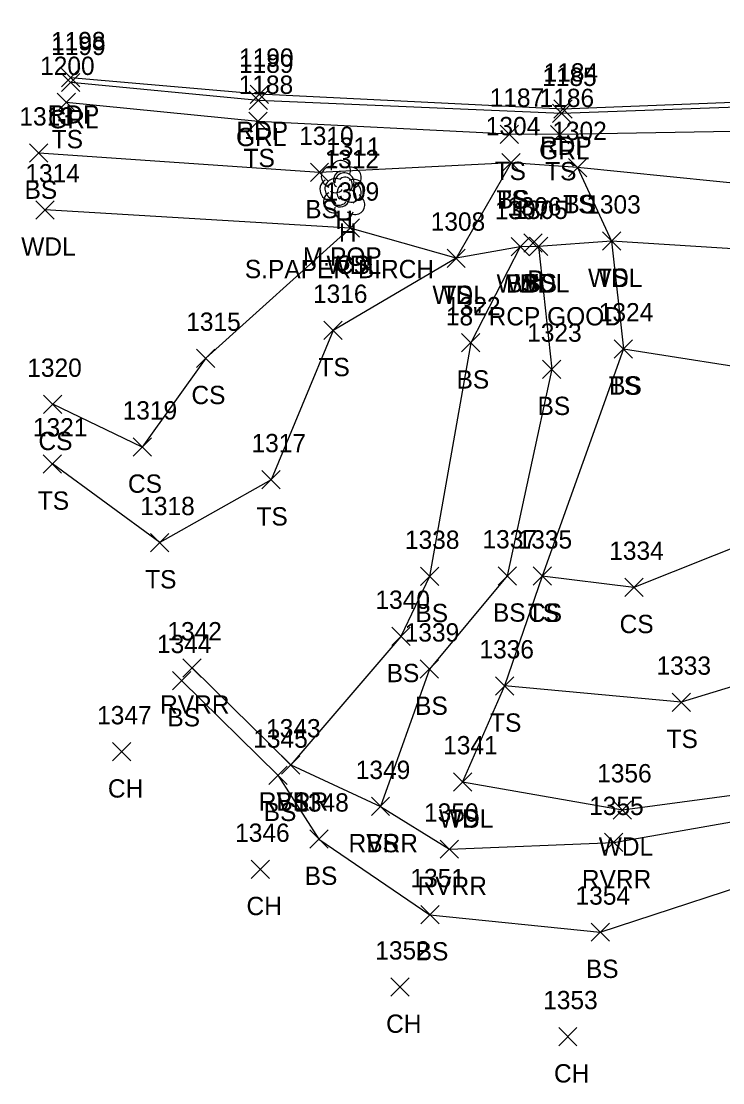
# Model space of a CAD drawing. Extents: x 1502119 to 1504100, y 606168 to 606406.
# Drawn here: x 1503596.2 to 1503672.8, y 606167.8 to 606283.7 of the extents above; entities that cross this region are included whole.
import ezdxf

# ---------------------------------------------------------------- set-up
doc = ezdxf.new("R2010")
doc.units = 0
for name, color, linetype in [('D_A', 7, 'Continuous'), ('D_C', 7, 'Continuous'), ('D_I', 7, 'Continuous'), ('D_TIC', 7, 'Continuous'), ('L_A', 7, 'Continuous'), ('L_C', 7, 'Continuous'), ('L_I', 7, 'Continuous'), ('L_TIC', 7, 'Continuous'), ('LAWA', 7, 'Continuous'), ('LAWE', 7, 'Continuous'), ('LELB', 7, 'Continuous'), ('LTD', 7, 'Continuous'), ('P_A', 7, 'Continuous'), ('P_I', 7, 'Continuous'), ('P_TIC', 7, 'Continuous'), ('PET', 7, 'Continuous'), ('R_A', 7, 'Continuous'), ('R_I', 7, 'Continuous'), ('R_TIC', 7, 'Continuous'), ('RGR', 7, 'Continuous')]:
    doc.layers.add(name, color=color, linetype=linetype)

msp = doc.modelspace()

# ---------------------------------------------------------------- linework, layer by layer
at = {"layer": 'D_TIC'}
for points in [[(1503651.06, 606258.48), (1503653.06, 606260.48)], [(1503653.06, 606258.48), (1503651.06, 606260.48)]]:
    msp.add_lwpolyline(points, dxfattribs=at)
at = {"layer": 'L_TIC'}
for points in [[(1503600.12, 606273.82), (1503602.12, 606275.82)], [(1503602.12, 606273.82), (1503600.12, 606275.82)], [(1503621.06, 606271.76), (1503623.06, 606273.76)], [(1503623.06, 606271.76), (1503621.06, 606273.76)], [(1503648.47, 606270.35), (1503650.47, 606272.35)], [(1503650.47, 606270.35), (1503648.47, 606272.35)], [(1503653.98, 606270.32), (1503655.98, 606272.32)], [(1503655.98, 606270.32), (1503653.98, 606272.32)], [(1503597.12, 606268.3), (1503599.12, 606270.3)], [(1503599.12, 606268.3), (1503597.12, 606270.3)], [(1503648.68, 606267.24), (1503650.68, 606269.24)], [(1503650.68, 606267.24), (1503648.68, 606269.24)], [(1503648.68, 606267.24), (1503650.68, 606269.24)], [(1503650.68, 606267.24), (1503648.68, 606269.24)], [(1503648.68, 606267.24), (1503650.68, 606269.24)], [(1503650.68, 606267.24), (1503648.68, 606269.24)], [(1503627.76, 606266.18), (1503629.76, 606268.18)], [(1503629.76, 606266.18), (1503627.76, 606268.18)], [(1503655.94, 606266.72), (1503657.94, 606268.72)], [(1503657.94, 606266.72), (1503655.94, 606268.72)], [(1503655.94, 606266.72), (1503657.94, 606268.72)], [(1503657.94, 606266.72), (1503655.94, 606268.72)], [(1503597.78, 606262.09), (1503599.78, 606264.09)], [(1503599.78, 606262.09), (1503597.78, 606264.09)], [(1503631.11, 606260.1), (1503633.11, 606262.1)], [(1503633.11, 606260.1), (1503631.11, 606262.1)], [(1503631.11, 606260.1), (1503633.11, 606262.1)], [(1503633.11, 606260.1), (1503631.11, 606262.1)], [(1503649.68, 606258.07), (1503651.68, 606260.07)], [(1503651.68, 606258.07), (1503649.68, 606260.07)], [(1503649.68, 606258.07), (1503651.68, 606260.07)], [(1503651.68, 606258.07), (1503649.68, 606260.07)], [(1503651.68, 606258.1), (1503653.68, 606260.1)], [(1503653.68, 606258.1), (1503651.68, 606260.1)], [(1503651.68, 606258.1), (1503653.68, 606260.1)], [(1503653.68, 606258.1), (1503651.68, 606260.1)], [(1503659.65, 606258.69), (1503661.65, 606260.69)], [(1503661.65, 606258.69), (1503659.65, 606260.69)], [(1503659.65, 606258.69), (1503661.65, 606260.69)], [(1503661.65, 606258.69), (1503659.65, 606260.69)], [(1503642.68, 606256.82), (1503644.68, 606258.82)], [(1503644.68, 606256.82), (1503642.68, 606258.82)], [(1503642.68, 606256.82), (1503644.68, 606258.82)], [(1503644.68, 606256.82), (1503642.68, 606258.82)], [(1503629.24, 606248.94), (1503631.24, 606250.94)], [(1503631.24, 606248.94), (1503629.24, 606250.94)], [(1503644.27, 606247.59), (1503646.27, 606249.59)], [(1503646.27, 606247.59), (1503644.27, 606249.59)], [(1503660.94, 606246.92), (1503662.94, 606248.92)], [(1503662.94, 606246.92), (1503660.94, 606248.92)], [(1503660.94, 606246.92), (1503662.94, 606248.92)], [(1503662.94, 606246.92), (1503660.94, 606248.92)], [(1503615.34, 606245.89), (1503617.34, 606247.89)], [(1503617.34, 606245.89), (1503615.34, 606247.89)], [(1503653.12, 606244.7), (1503655.12, 606246.7)], [(1503655.12, 606244.7), (1503653.12, 606246.7)], [(1503598.64, 606240.87), (1503600.64, 606242.87)], [(1503600.64, 606240.87), (1503598.64, 606242.87)], [(1503608.41, 606236.21), (1503610.41, 606238.21)], [(1503610.41, 606236.21), (1503608.41, 606238.21)], [(1503598.6, 606234.36), (1503600.6, 606236.36)], [(1503600.6, 606234.36), (1503598.6, 606236.36)], [(1503622.47, 606232.64), (1503624.47, 606234.64)], [(1503624.47, 606232.64), (1503622.47, 606234.64)], [(1503610.32, 606225.77), (1503612.32, 606227.77)], [(1503612.32, 606225.77), (1503610.32, 606227.77)], [(1503639.78, 606222.09), (1503641.78, 606224.09)], [(1503641.78, 606222.09), (1503639.78, 606224.09)], [(1503648.25, 606222.14), (1503650.25, 606224.14)], [(1503650.25, 606222.14), (1503648.25, 606224.14)], [(1503652.08, 606222.12), (1503654.08, 606224.12)], [(1503654.08, 606222.12), (1503652.08, 606224.12)], [(1503652.08, 606222.12), (1503654.08, 606224.12)], [(1503654.08, 606222.12), (1503652.08, 606224.12)], [(1503662.08, 606220.89), (1503664.08, 606222.89)], [(1503664.08, 606220.89), (1503662.08, 606222.89)], [(1503636.65, 606215.54), (1503638.65, 606217.54)], [(1503638.65, 606215.54), (1503636.65, 606217.54)], [(1503613.85, 606212.1), (1503615.85, 606214.1)], [(1503615.85, 606212.1), (1503613.85, 606214.1)], [(1503639.76, 606211.97), (1503641.76, 606213.97)], [(1503641.76, 606211.97), (1503639.76, 606213.97)], [(1503612.71, 606210.71), (1503614.71, 606212.71)], [(1503614.71, 606210.71), (1503612.71, 606212.71)], [(1503647.97, 606210.13), (1503649.97, 606212.13)], [(1503649.97, 606210.13), (1503647.97, 606212.13)], [(1503647.97, 606210.13), (1503649.97, 606212.13)], [(1503649.97, 606210.13), (1503647.97, 606212.13)], [(1503667.25, 606208.35), (1503669.25, 606210.35)], [(1503669.25, 606208.35), (1503667.25, 606210.35)], [(1503606.17, 606202.94), (1503608.17, 606204.94)], [(1503608.17, 606202.94), (1503606.17, 606204.94)], [(1503624.62, 606201.51), (1503626.62, 606203.51)], [(1503626.62, 606201.51), (1503624.62, 606203.51)], [(1503624.62, 606201.51), (1503626.62, 606203.51)], [(1503626.62, 606201.51), (1503624.62, 606203.51)], [(1503623.23, 606200.38), (1503625.23, 606202.38)], [(1503625.23, 606200.38), (1503623.23, 606202.38)], [(1503643.38, 606199.66), (1503645.38, 606201.66)], [(1503645.38, 606199.66), (1503643.38, 606201.66)], [(1503643.38, 606199.66), (1503645.38, 606201.66)], [(1503645.38, 606199.66), (1503643.38, 606201.66)], [(1503634.42, 606196.97), (1503636.42, 606198.97)], [(1503636.42, 606196.97), (1503634.42, 606198.97)], [(1503634.42, 606196.97), (1503636.42, 606198.97)], [(1503636.42, 606196.97), (1503634.42, 606198.97)], [(1503660.82, 606196.6), (1503662.82, 606198.6)], [(1503662.82, 606196.6), (1503660.82, 606198.6)], [(1503627.7, 606193.41), (1503629.7, 606195.41)], [(1503629.7, 606193.41), (1503627.7, 606195.41)], [(1503659.89, 606193.04), (1503661.89, 606195.04)], [(1503661.89, 606193.04), (1503659.89, 606195.04)], [(1503641.95, 606192.31), (1503643.95, 606194.31)], [(1503643.95, 606192.31), (1503641.95, 606194.31)], [(1503621.3, 606190.11), (1503623.3, 606192.11)], [(1503623.3, 606190.11), (1503621.3, 606192.11)], [(1503639.82, 606185.16), (1503641.82, 606187.16)], [(1503641.82, 606185.16), (1503639.82, 606187.16)], [(1503658.4, 606183.25), (1503660.4, 606185.25)], [(1503660.4, 606183.25), (1503658.4, 606185.25)], [(1503636.54, 606177.26), (1503638.54, 606179.26)], [(1503638.54, 606177.26), (1503636.54, 606179.26)], [(1503654.87, 606171.84), (1503656.87, 606173.84)], [(1503656.87, 606171.84), (1503654.87, 606173.84)]]:
    msp.add_lwpolyline(points, dxfattribs=at)
at = {"layer": 'LAWA'}
for points in [[(1503949.06, 606292.95), (1503922.72, 606291.41), (1503895.88, 606293.14), (1503871.23, 606284.55), (1503848.49, 606280.84), (1503822.63, 606273.75), (1503793.16, 606269.59), (1503770.58, 606267.1), (1503744.52, 606264.72), (1503721.39, 606263.89), (1503714.66, 606265.31), (1503698.22, 606260.24), (1503685.38, 606258.11), (1503660.65, 606259.69), (1503652.68, 606259.1), (1503650.68, 606259.07), (1503643.68, 606257.82), (1503632.11, 606261.1), (1503598.78, 606263.09)], [(1503644.38, 606200.66), (1503661.82, 606197.6), (1503681.92, 606200.3), (1503697.7, 606204.96), (1503718.32, 606211.61), (1503749.72, 606205.75), (1503773.98, 606210.33), (1503804.12, 606207.66), (1503814.72, 606212.71), (1503825.12, 606213.47), (1503835.31, 606218.59), (1503851.96, 606217.91), (1503869.14, 606226.79), (1503894.25, 606229.09), (1503902.71, 606239.52), (1503913.47, 606247.57)]]:
    msp.add_lwpolyline(points, dxfattribs=at)
at = {"layer": 'LAWE'}
msp.add_lwpolyline([(1503614.85, 606213.1), (1503625.62, 606202.51), (1503635.42, 606197.97), (1503642.95, 606193.31), (1503660.89, 606194.04), (1503681.2, 606197.62), (1503698.42, 606201.39), (1503720.62, 606206.39), (1503749.7, 606202.44), (1503775.92, 606206.14), (1503802.08, 606202.28), (1503818.9, 606205.49), (1503835.44, 606207.89), (1503847.03, 606211.3), (1503876.78, 606218.57), (1503896.13, 606221.77), (1503905.66, 606233.48), (1503922.02, 606244.01), (1503934.31, 606243.71)], dxfattribs=at)
at = {"layer": 'LELB'}
for points in [[(1504084.2, 606316.18), (1504049.45, 606313.99), (1504016.18, 606312.8), (1504000.76, 606312.78), (1503990.22, 606311.65), (1503980.1, 606310.35), (1503956.75, 606307.04), (1503915.14, 606300.95), (1503869.77, 606289.77), (1503847.82, 606285.43), (1503820.78, 606281.87), (1503792.45, 606279.04), (1503767.54, 606276.84), (1503743.42, 606274.71), (1503718.48, 606272.4), (1503713.68, 606272.36), (1503654.98, 606271.32), (1503649.47, 606271.35), (1503622.06, 606272.76), (1503601.12, 606274.82)], [(1503984.83, 606255.06), (1503973.29, 606256.69), (1503955.93, 606260.62), (1503952.28, 606267.45), (1503924.4, 606275.03), (1503909.61, 606278), (1503896.78, 606282.99), (1503877.54, 606272.17), (1503862.1, 606272.45), (1503836.9, 606266.22), (1503825.65, 606259.98), (1503818.28, 606261.16), (1503806.2, 606257.22), (1503801.33, 606241.79), (1503784.67, 606238.5), (1503757.1, 606237.25), (1503731.6, 606237.76), (1503710.27, 606237.78), (1503692.02, 606229.45), (1503676.15, 606227.07), (1503663.08, 606221.89), (1503653.08, 606223.12)], [(1503649.68, 606268.24), (1503628.76, 606267.18), (1503598.12, 606269.3)], [(1503649.68, 606268.24), (1503643.68, 606257.82), (1503630.24, 606249.94), (1503623.47, 606233.64), (1503611.32, 606226.77), (1503599.6, 606235.36)], [(1503714.66, 606265.31), (1503697.47, 606267.28), (1503682.2, 606265.19), (1503656.94, 606267.72), (1503649.68, 606268.24)], [(1503656.94, 606267.72), (1503660.65, 606259.69), (1503661.94, 606247.92), (1503653.08, 606223.12), (1503648.97, 606211.13), (1503644.38, 606200.66)], [(1503632.11, 606261.1), (1503616.34, 606246.89), (1503609.41, 606237.21), (1503599.64, 606241.87)], [(1503650.68, 606259.07), (1503645.27, 606248.59), (1503640.78, 606223.09), (1503637.65, 606216.54), (1503625.62, 606202.51)], [(1503652.68, 606259.1), (1503654.12, 606245.7), (1503649.25, 606223.14), (1503640.76, 606212.97), (1503635.42, 606197.97)], [(1503930, 606245.46), (1503918.92, 606249.17), (1503904.84, 606258.51), (1503879.8, 606256.17), (1503860.62, 606251.71), (1503849.74, 606241), (1503840.87, 606237.08), (1503831.29, 606226.33), (1503824.17, 606224.52), (1503818.07, 606222.32), (1503808.71, 606221.45), (1503786.64, 606226.93), (1503757.01, 606228.26), (1503733.84, 606223.62), (1503713.55, 606226.86), (1503694.71, 606218.05), (1503680.4, 606213.07), (1503668.25, 606209.35), (1503648.97, 606211.13)], [(1503661.94, 606247.92), (1503679.1, 606245.25), (1503703.2, 606245.4)], [(1503613.71, 606211.71), (1503624.23, 606201.38), (1503628.7, 606194.41), (1503640.82, 606186.16), (1503659.4, 606184.25), (1503680.75, 606191.25), (1503695.72, 606193.45), (1503722.13, 606200.99), (1503749.25, 606197.03), (1503775.84, 606202.19), (1503801.63, 606198.61), (1503818.14, 606200.65), (1503835.99, 606205), (1503847.21, 606209.11), (1503877.12, 606216.19), (1503896.03, 606218.36), (1503907.7, 606226.44), (1503929.55, 606235.83)]]:
    msp.add_lwpolyline(points, dxfattribs=at)
at = {"layer": 'LTD'}
for p, q in [((1503631.04, 606266), (1503631.04, 606266)), ((1503631.04, 606266), (1503631.04, 606266)), ((1503631.43, 606264.64), (1503631.43, 606264.64)), ((1503631.43, 606264.64), (1503631.43, 606264.64))]:
    msp.add_line(p, q, dxfattribs=at)
for centre in [(1503631.09, 606267.43), (1503631.48, 606266.08)]:
    msp.add_arc(centre, 1.05, 335.5272, 180.9563, dxfattribs=at)
for centre, major_axis, ratio, start_param, end_param in [((1503630.25, 606266.66), (1.21, -0.51), 0.895232, 1.570796, 4.712389), ((1503632.08, 606266.58), (-1.14, -0.48), 0.949671, 1.570796, 4.712389), ((1503630.83, 606266.45), (-0.208, -0.792), 0.645439, 3.141593, 6.283185), ((1503631.54, 606265.83), (-0.5, 0.667), 0.989748, 3.141593, 6.283185), ((1503629.96, 606265.29), (0.58, -1.04), 0.959034, 3.141593, 6.283185), ((1503630.64, 606265.31), (1.21, -0.51), 0.895232, 1.570796, 4.712389), ((1503631.22, 606265.1), (-0.208, -0.792), 0.645439, 3.141593, 6.283185), ((1503632.04, 606265.16), (-1.09, 0.79), 0.841452, 1.570796, 4.712389), ((1503632.47, 606265.23), (-1.14, -0.48), 0.949671, 1.570796, 4.712389), ((1503630.35, 606263.93), (0.58, -1.04), 0.959034, 3.141593, 6.283185), ((1503631.04, 606264.5), (0.26, 1.06), 0.942809, 1.570796, 4.712389), ((1503630.59, 606265.25), (-0.625, -0.083), 0.423636, 0, 3.141593), ((1503631.93, 606264.48), (-0.5, 0.667), 0.989748, 3.141593, 6.283185), ((1503632.43, 606263.81), (-1.09, 0.79), 0.841452, 1.570796, 4.712389), ((1503631.43, 606263.14), (0.26, 1.06), 0.942809, 1.570796, 4.712389), ((1503630.97, 606263.89), (-0.625, -0.083), 0.423636, 0, 3.141593)]:
    msp.add_ellipse(centre, major_axis=major_axis, ratio=ratio, start_param=start_param, end_param=end_param, dxfattribs=at)
at = {"layer": 'P_TIC'}
for points in [[(1503600.58, 606276.52), (1503602.58, 606278.52)], [(1503602.58, 606276.52), (1503600.58, 606278.52)], [(1503621.19, 606274.72), (1503623.19, 606276.72)], [(1503623.19, 606274.72), (1503621.19, 606276.72)], [(1503654.34, 606273.1), (1503656.34, 606275.1)], [(1503656.34, 606273.1), (1503654.34, 606275.1)]]:
    msp.add_lwpolyline(points, dxfattribs=at)
at = {"layer": 'PET'}
msp.add_lwpolyline([(1504084.52, 606320.63), (1504050.65, 606320.45), (1504000.43, 606315.8), (1503956.16, 606310.12), (1503915.05, 606304.21), (1503867.85, 606296.91), (1503814.4, 606288.86), (1503766.38, 606281.21), (1503714.75, 606276.43), (1503655.34, 606274.1), (1503622.19, 606275.72), (1503601.58, 606277.52)], dxfattribs=at)
at = {"layer": 'R_TIC'}
for points in [[(1503600.6, 606276), (1503602.6, 606278)], [(1503602.6, 606276), (1503600.6, 606278)], [(1503621.1, 606274.05), (1503623.1, 606276.05)], [(1503623.1, 606274.05), (1503621.1, 606276.05)], [(1503654.19, 606272.62), (1503656.19, 606274.62)], [(1503656.19, 606272.62), (1503654.19, 606274.62)]]:
    msp.add_lwpolyline(points, dxfattribs=at)
at = {"layer": 'RGR'}
msp.add_lwpolyline([(1504084.44, 606319.87), (1504050.55, 606319.53), (1504000.64, 606315), (1503956.05, 606309.11), (1503915.05, 606302.99), (1503867.97, 606295.96), (1503814.82, 606287.72), (1503766.2, 606280.53), (1503714.79, 606275.76), (1503655.19, 606273.62), (1503622.1, 606275.05), (1503601.6, 606277)], dxfattribs=at)

# ---------------------------------------------------------------- texts
at = {"layer": 'D_A'}
msp.add_text('P', height=2, dxfattribs=at).set_placement((1503651.44, 606254.48))
at = {"layer": 'D_C'}
msp.add_text('18" RCP GOOD', height=2, dxfattribs=at).set_placement((1503642.55, 606250.48))
at = {"layer": 'D_I'}
msp.add_text('1306', height=2, dxfattribs=at).set_placement((1503649.23, 606262.48))
at = {"layer": 'L_A'}
for s, p in [('TS', (1503599.53, 606269.82)), ('TS', (1503620.47, 606267.76)), ('TS', (1503647.88, 606266.35)), ('TS', (1503653.39, 606266.32)), ('BS', (1503596.56, 606264.3)), ('TS', (1503648.09, 606263.24)), ('BS', (1503648.12, 606263.24)), ('BS', (1503648.12, 606263.24)), ('TS', (1503655.35, 606262.72)), ('BS', (1503655.38, 606262.72)), ('BS', (1503627.2, 606262.18)), ('H', (1503630.48, 606261)), ('H', (1503630.87, 606259.64)), ('WDL', (1503596.2, 606258.09)), ('WDL', (1503629.53, 606256.1)), ('CS', (1503630.55, 606256.1)), ('WDL', (1503658.07, 606254.69)), ('TS', (1503659.06, 606254.69)), ('WDL', (1503648.09, 606254.07)), ('BS', (1503649.12, 606254.07)), ('WDL', (1503650.1, 606254.1)), ('BS', (1503651.12, 606254.1)), ('WDL', (1503641.09, 606252.82)), ('TS', (1503642.09, 606252.82)), ('TS', (1503628.65, 606244.94)), ('BS', (1503643.72, 606243.59)), ('TS', (1503660.35, 606242.92)), ('BS', (1503660.38, 606242.92)), ('CS', (1503614.78, 606241.89)), ('BS', (1503652.56, 606240.7)), ('CS', (1503598.08, 606236.87)), ('CS', (1503607.85, 606232.21)), ('TS', (1503598.01, 606230.36)), ('TS', (1503621.88, 606228.64)), ('TS', (1503609.73, 606221.77)), ('BS', (1503639.23, 606218.09)), ('BS', (1503647.69, 606218.14)), ('TS', (1503651.49, 606218.12)), ('CS', (1503651.52, 606218.12)), ('CS', (1503661.52, 606216.89)), ('BS', (1503636.09, 606211.54)), ('RVRR', (1503611.36, 606208.1)), ('BS', (1503639.2, 606207.97)), ('BS', (1503612.15, 606206.71)), ('TS', (1503647.38, 606206.13)), ('TS', (1503647.38, 606206.13)), ('TS', (1503666.65, 606204.35)), ('CH', (1503605.66, 606198.94)), ('RVRR', (1503622.13, 606197.51)), ('BS', (1503624.06, 606197.51)), ('BS', (1503622.67, 606196.38)), ('WDL', (1503641.8, 606195.66)), ('TS', (1503642.79, 606195.66)), ('RVRR', (1503631.93, 606192.97)), ('BS', (1503633.86, 606192.97)), ('WDL', (1503659.24, 606192.6)), ('BS', (1503627.14, 606189.41)), ('RVRR', (1503639.46, 606188.31)), ('RVRR', (1503657.4, 606189.04)), ('CH', (1503620.79, 606186.11)), ('BS', (1503639.26, 606181.16)), ('BS', (1503657.84, 606179.25)), ('CH', (1503636.03, 606173.26)), ('CH', (1503654.36, 606167.84))]:
    msp.add_text(s, height=2, dxfattribs=at).set_placement(p)
at = {"layer": 'L_C'}
for s, p in [('M.POP', (1503626.94, 606257)), ('S.PAPER BIRCH', (1503620.61, 606255.64))]:
    msp.add_text(s, height=2, dxfattribs=at).set_placement(p)
at = {"layer": 'L_I'}
for s, p in [('1200', (1503598.26, 606277.82)), ('1188', (1503619.94, 606275.76)), ('1187', (1503647.34, 606274.35)), ('1186', (1503652.79, 606274.32)), ('1313', (1503596, 606272.3)), ('1304', (1503646.91, 606271.24)), ('1304', (1503646.91, 606271.24)), ('1304', (1503646.91, 606271.24)), ('1302', (1503654.17, 606270.72)), ('1302', (1503654.17, 606270.72)), ('1310', (1503626.54, 606270.18)), ('1311', (1503629.48, 606269)), ('1312', (1503629.31, 606267.64)), ('1314', (1503596.65, 606266.09)), ('1309', (1503629.33, 606264.1)), ('1309', (1503629.33, 606264.1)), ('1303', (1503657.88, 606262.69)), ('1303', (1503657.88, 606262.69)), ('1307', (1503647.9, 606262.07)), ('1307', (1503647.9, 606262.07)), ('1305', (1503649.91, 606262.1)), ('1305', (1503649.91, 606262.1)), ('1308', (1503640.9, 606260.82)), ('1308', (1503640.9, 606260.82)), ('1316', (1503628.05, 606252.94)), ('1322', (1503642.58, 606251.59)), ('1324', (1503659.25, 606250.92)), ('1324', (1503659.25, 606250.92)), ('1315', (1503614.21, 606249.89)), ('1323', (1503651.43, 606248.7)), ('1320', (1503596.86, 606244.87)), ('1319', (1503607.27, 606240.21)), ('1321', (1503597.47, 606238.36)), ('1317', (1503621.34, 606236.64)), ('1318', (1503609.19, 606229.77)), ('1338', (1503638.09, 606226.09)), ('1337', (1503646.55, 606226.14)), ('1335', (1503650.39, 606226.12)), ('1335', (1503650.39, 606226.12)), ('1334', (1503660.39, 606224.89)), ('1340', (1503634.87, 606219.54)), ('1342', (1503612.15, 606216.1)), ('1339', (1503638.06, 606215.97)), ('1344', (1503611.02, 606214.71)), ('1336', (1503646.22, 606214.13)), ('1336', (1503646.22, 606214.13)), ('1333', (1503665.55, 606212.35)), ('1347', (1503604.48, 606206.94)), ('1343', (1503622.93, 606205.51)), ('1343', (1503622.93, 606205.51)), ('1345', (1503621.53, 606204.38)), ('1341', (1503642.26, 606203.66)), ('1341', (1503642.26, 606203.66)), ('1349', (1503632.72, 606200.97)), ('1349', (1503632.72, 606200.97)), ('1356', (1503659.07, 606200.6)), ('1348', (1503626.01, 606197.41)), ('1355', (1503658.2, 606197.04)), ('1350', (1503640.17, 606196.31)), ('1346', (1503619.55, 606194.11)), ('1351', (1503638.69, 606189.16)), ('1354', (1503656.71, 606187.25)), ('1352', (1503634.85, 606181.26)), ('1353', (1503653.18, 606175.84))]:
    msp.add_text(s, height=2, dxfattribs=at).set_placement(p)
at = {"layer": 'P_A'}
for p in [(1503599.07, 606272.52), (1503619.68, 606270.72), (1503652.83, 606269.1)]:
    msp.add_text('RDP', height=2, dxfattribs=at).set_placement(p)
at = {"layer": 'P_I'}
for s, p in [('1198', (1503599.45, 606280.52)), ('1190', (1503619.98, 606278.72)), ('1184', (1503653.22, 606277.1))]:
    msp.add_text(s, height=2, dxfattribs=at).set_placement(p)
at = {"layer": 'R_A'}
for p in [(1503599.14, 606272), (1503619.65, 606270.05), (1503652.74, 606268.62)]:
    msp.add_text('GRL', height=2, dxfattribs=at).set_placement(p)
at = {"layer": 'R_I'}
for s, p in [('1199', (1503599.47, 606280)), ('1189', (1503619.97, 606278.05)), ('1185', (1503653.07, 606276.62))]:
    msp.add_text(s, height=2, dxfattribs=at).set_placement(p)

doc.saveas('drawing.dxf')
